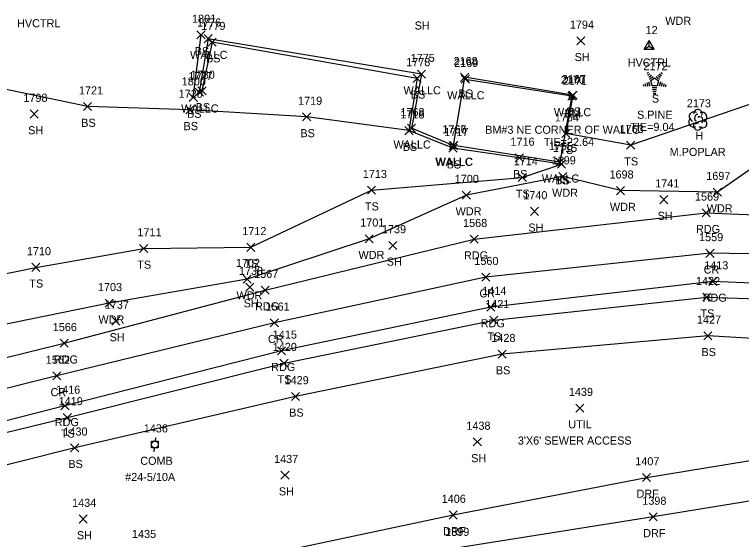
# Model space of a CAD drawing. Extents: x 1609623 to 1616187, y 756677 to 762826.
# Drawn here: x 1609877.2 to 1610056.5, y 761685.5 to 761815 of the extents above; entities that cross this region are included whole.
import ezdxf

# ---------------------------------------------------------------- set-up
doc = ezdxf.new("R2010")
doc.units = 0
for name, color, linetype in [('C_A', 7, 'Continuous'), ('C_C', 7, 'Continuous'), ('C_I', 7, 'Continuous'), ('CPBM', 7, 'Continuous'), ('CPSM', 7, 'Continuous'), ('L_A', 7, 'Continuous'), ('L_C', 7, 'Continuous'), ('L_I', 7, 'Continuous'), ('L_TIC', 7, 'Continuous'), ('LAWA', 7, 'Continuous'), ('LELB', 7, 'Continuous'), ('LTC', 7, 'Continuous'), ('LTD', 7, 'Continuous'), ('LW', 7, 'Continuous'), ('P_A', 7, 'Continuous'), ('P_I', 7, 'Continuous'), ('P_TIC', 7, 'Continuous'), ('PEU', 7, 'Continuous'), ('PRC', 7, 'Continuous'), ('R_A', 7, 'Continuous'), ('R_I', 7, 'Continuous'), ('R_TIC', 7, 'Continuous'), ('RDF', 7, 'Continuous'), ('U_A', 7, 'Continuous'), ('U_C', 7, 'Continuous'), ('U_I', 7, 'Continuous'), ('UDEFAULT', 7, 'Continuous'), ('UP', 7, 'Continuous')]:
    doc.layers.add(name, color=color, linetype=linetype)

msp = doc.modelspace()

# ---------------------------------------------------------------- linework, layer by layer
at = {"layer": 'CPBM'}
for p, q in [((1610014.04, 761794.09), (1610014.04, 761795.09)), ((1610014.04, 761795.09), (1610015.04, 761795.09)), ((1610015.04, 761794.09), (1610014.04, 761794.09)), ((1610014.54, 761794.59), (1610014.54, 761794.59)), ((1610014.54, 761794.59), (1610014.54, 761794.59)), ((1610015.04, 761795.09), (1610015.04, 761794.09))]:
    msp.add_line(p, q, dxfattribs=at)
at = {"layer": 'CPSM'}
for p, q in [((1610032.48, 761806.47), (1610033.73, 761808.63)), ((1610034.98, 761806.47), (1610033.73, 761808.63)), ((1610033.73, 761807.19), (1610033.73, 761808.63)), ((1610032.48, 761806.47), (1610033.73, 761807.19)), ((1610033.73, 761807.19), (1610033.73, 761807.19)), ((1610033.73, 761807.19), (1610034.98, 761806.47)), ((1610032.48, 761806.47), (1610034.98, 761806.47))]:
    msp.add_line(p, q, dxfattribs=at)
at = {"layer": 'L_TIC'}
for points in [[(1609922.17, 761808.99), (1609924.17, 761810.99)], [(1609924.17, 761808.99), (1609922.17, 761810.99)], [(1609923.94, 761808.06), (1609925.94, 761810.06)], [(1609925.94, 761808.06), (1609923.94, 761810.06)], [(1609924.95, 761807.21), (1609926.95, 761809.21)], [(1609926.95, 761807.21), (1609924.95, 761809.21)], [(1610015.85, 761807.53), (1610017.85, 761809.53)], [(1610017.85, 761807.53), (1610015.85, 761809.53)], [(1609976.58, 761799.32), (1609978.58, 761801.32)], [(1609978.58, 761799.32), (1609976.58, 761801.32)], [(1609975.48, 761798.27), (1609977.48, 761800.27)], [(1609977.48, 761798.27), (1609975.48, 761800.27)], [(1609987.2, 761798.53), (1609989.2, 761800.53)], [(1609989.2, 761798.53), (1609987.2, 761800.53)], [(1609987.36, 761798.09), (1609989.36, 761800.09)], [(1609989.36, 761798.09), (1609987.36, 761800.09)], [(1609921.75, 761794.84), (1609923.75, 761796.84)], [(1609923.75, 761794.84), (1609921.75, 761796.84)], [(1609922.41, 761795.17), (1609924.41, 761797.17)], [(1609924.41, 761795.17), (1609922.41, 761797.17)], [(1610013.68, 761793.92), (1610015.68, 761795.92)], [(1610015.68, 761793.92), (1610013.68, 761795.92)], [(1610013.92, 761794.1), (1610015.92, 761796.1)], [(1610015.92, 761794.1), (1610013.92, 761796.1)], [(1609920.27, 761793.53), (1609922.27, 761795.53)], [(1609922.27, 761793.53), (1609920.27, 761795.53)], [(1609894.19, 761791.3), (1609896.19, 761793.3)], [(1609896.19, 761791.3), (1609894.19, 761793.3)], [(1609919.43, 761790.48), (1609921.43, 761792.48)], [(1609921.43, 761790.48), (1609919.43, 761792.48)], [(1609881.04, 761789.47), (1609883.04, 761791.47)], [(1609883.04, 761789.47), (1609881.04, 761791.47)], [(1609948.24, 761788.75), (1609950.24, 761790.75)], [(1609950.24, 761788.75), (1609948.24, 761790.75)], [(1609973.47, 761785.37), (1609975.47, 761787.37)], [(1609975.47, 761785.37), (1609973.47, 761787.37)], [(1609974.1, 761785.94), (1609976.1, 761787.94)], [(1609976.1, 761785.94), (1609974.1, 761787.94)], [(1610012.18, 761784.65), (1610014.18, 761786.65)], [(1610014.18, 761784.65), (1610012.18, 761786.65)], [(1609984.41, 761781.67), (1609986.41, 761783.67)], [(1609986.41, 761781.67), (1609984.41, 761783.67)], [(1609984.54, 761781.69), (1609986.54, 761783.69)], [(1609986.54, 761781.69), (1609984.54, 761783.69)], [(1610028.16, 761781.79), (1610030.16, 761783.79)], [(1610030.16, 761781.79), (1610028.16, 761783.79)], [(1609984.32, 761781.03), (1609986.32, 761783.03)], [(1609986.32, 761781.03), (1609984.32, 761783.03)], [(1610000.68, 761778.63), (1610002.68, 761780.63)], [(1610002.68, 761778.63), (1610000.68, 761780.63)], [(1610010.71, 761777.56), (1610012.71, 761779.56)], [(1610012.71, 761777.56), (1610010.71, 761779.56)], [(1610011.12, 761777.1), (1610013.12, 761779.1)], [(1610013.12, 761777.1), (1610011.12, 761779.1)], [(1610011.12, 761777.1), (1610013.12, 761779.1)], [(1610013.12, 761777.1), (1610011.12, 761779.1)], [(1610011.41, 761774.03), (1610013.41, 761776.03)], [(1610013.41, 761774.03), (1610011.41, 761776.03)], [(1610001.42, 761773.81), (1610003.42, 761775.81)], [(1610003.42, 761773.81), (1610001.42, 761775.81)], [(1609964.21, 761770.67), (1609966.21, 761772.67)], [(1609966.21, 761770.67), (1609964.21, 761772.67)], [(1610025.67, 761770.55), (1610027.67, 761772.55)], [(1610027.67, 761770.55), (1610025.67, 761772.55)], [(1609987.62, 761769.46), (1609989.62, 761771.46)], [(1609989.62, 761769.46), (1609987.62, 761771.46)], [(1610049.54, 761770.19), (1610051.54, 761772.19)], [(1610051.54, 761770.19), (1610049.54, 761772.19)], [(1610036.32, 761768.34), (1610038.32, 761770.34)], [(1610038.32, 761768.34), (1610036.32, 761770.34)], [(1610004.44, 761765.44), (1610006.44, 761767.44)], [(1610006.44, 761765.44), (1610004.44, 761767.44)], [(1609963.66, 761758.68), (1609965.66, 761760.68)], [(1609965.66, 761758.68), (1609963.66, 761760.68)], [(1609908.04, 761756.29), (1609910.04, 761758.29)], [(1609910.04, 761756.29), (1609908.04, 761758.29)], [(1609934.48, 761756.57), (1609936.48, 761758.57)], [(1609936.48, 761756.57), (1609934.48, 761758.57)], [(1609969.5, 761757.04), (1609971.5, 761759.04)], [(1609971.5, 761757.04), (1609969.5, 761759.04)], [(1609881.42, 761751.62), (1609883.42, 761753.62)], [(1609883.42, 761751.62), (1609881.42, 761753.62)], [(1609933.55, 761748.72), (1609935.55, 761750.72)], [(1609935.55, 761748.72), (1609933.55, 761750.72)], [(1609934.22, 761746.74), (1609936.22, 761748.74)], [(1609936.22, 761746.74), (1609934.22, 761748.74)], [(1610046.96, 761744.26), (1610048.96, 761746.26)], [(1610048.96, 761744.26), (1610046.96, 761746.26)], [(1609899.52, 761742.76), (1609901.52, 761744.76)], [(1609901.52, 761742.76), (1609899.52, 761744.76)], [(1609901.14, 761738.39), (1609903.14, 761740.39)], [(1609903.14, 761738.39), (1609901.14, 761740.39)], [(1609994.4, 761738.57), (1609996.4, 761740.57)], [(1609996.4, 761738.57), (1609994.4, 761740.57)], [(1610047.19, 761734.72), (1610049.19, 761736.72)], [(1610049.19, 761734.72), (1610047.19, 761736.72)], [(1609996.47, 761730.21), (1609998.47, 761732.21)], [(1609998.47, 761730.21), (1609996.47, 761732.21)], [(1609942.65, 761728), (1609944.65, 761730)], [(1609944.65, 761728), (1609942.65, 761730)], [(1609945.49, 761719.77), (1609947.49, 761721.77)], [(1609947.49, 761719.77), (1609945.49, 761721.77)], [(1609889.2, 761714.59), (1609891.2, 761716.59)], [(1609891.2, 761714.59), (1609889.2, 761716.59)], [(1609990.32, 761708.53), (1609992.32, 761710.53)], [(1609992.32, 761708.53), (1609990.32, 761710.53)], [(1609891.01, 761707.1), (1609893.01, 761709.1)], [(1609893.01, 761707.1), (1609891.01, 761709.1)], [(1609942.89, 761700.33), (1609944.89, 761702.33)], [(1609944.89, 761700.33), (1609942.89, 761702.33)], [(1609893.08, 761689.51), (1609895.08, 761691.51)], [(1609895.08, 761689.51), (1609893.08, 761691.51)]]:
    msp.add_lwpolyline(points, dxfattribs=at)
at = {"layer": 'LAWA'}
msp.add_lwpolyline([(1610105.26, 761813.02), (1610140.61, 761813.42), (1610167.68, 761812.65), (1610195.19, 761811.82), (1610200.47, 761794.62), (1610201.65, 761767.6), (1610187.83, 761765.14), (1610147.91, 761771.28), (1610109.49, 761778.29), (1610068.49, 761778.93), (1610059.44, 761777.35), (1610050.54, 761771.19), (1610026.67, 761771.55), (1610012.41, 761775.03), (1609988.62, 761770.46), (1609964.66, 761759.68), (1609934.55, 761749.72), (1609900.52, 761743.76), (1609861.36, 761735.79), (1609834.63, 761731.47), (1609803.94, 761726.14)], dxfattribs=at)
at = {"layer": 'LELB'}
for points in [[(1609921.27, 761794.53), (1609923.17, 761809.99)], [(1609976.48, 761799.27), (1609925.95, 761808.21), (1609923.41, 761796.17)], [(1610012.12, 761778.1), (1610001.68, 761779.63), (1609985.32, 761782.03), (1609974.47, 761786.37), (1609949.24, 761789.75), (1609920.43, 761791.48), (1609895.19, 761792.3), (1609862.07, 761799.25), (1609844.22, 761803.39), (1609837.25, 761792.78), (1609798.06, 761802.79)], [(1609988.2, 761799.53), (1609985.41, 761782.67)], [(1610014.92, 761795.1), (1609988.2, 761799.53)], [(1609976.48, 761799.27), (1609974.47, 761786.37)], [(1610014.92, 761795.1), (1610013.18, 761785.65)], [(1610068.13, 761791.39), (1610060.09, 761793.42), (1610029.16, 761782.79), (1610013.18, 761785.65)], [(1609797.77, 761751.53), (1609825.21, 761750.42), (1609849.09, 761745.85), (1609882.42, 761752.62), (1609909.04, 761757.29), (1609935.48, 761757.57), (1609965.21, 761771.67), (1610002.42, 761774.81), (1610012.12, 761778.1)], [(1609807.34, 761695.39), (1609890.2, 761715.59), (1609943.65, 761729), (1609995.4, 761739.57), (1610047.96, 761745.26), (1610095.6, 761743.67), (1610138.67, 761738.82), (1610134.33, 761731.12)], [(1610134.33, 761731.12), (1610095.12, 761732.91), (1610048.19, 761735.72), (1609997.47, 761731.21), (1609946.49, 761720.77), (1609892.01, 761708.1), (1609809.24, 761687.22)]]:
    msp.add_lwpolyline(points, dxfattribs=at)
at = {"layer": 'LTC'}
for p, q in [((1610033.19, 761800.5), (1610033.54, 761800.76)), ((1610033.4, 761800.03), (1610033.93, 761800.42)), ((1610033.61, 761799.57), (1610034.31, 761800.08)), ((1610033.82, 761799.1), (1610034.69, 761799.74)), ((1610034.04, 761798.65), (1610035.05, 761799.38)), ((1610035.05, 761799.38), (1610036.05, 761798.66)), ((1610035.47, 761799.7), (1610036.28, 761799.11)), ((1610035.84, 761800.04), (1610036.52, 761799.55)), ((1610036.21, 761800.39), (1610036.76, 761799.99)), ((1610036.59, 761800.74), (1610037.01, 761800.44)), ((1610032.22, 761797.78), (1610032.37, 761797.31)), ((1610032.68, 761798), (1610032.89, 761797.34)), ((1610033.13, 761798.21), (1610033.4, 761797.38)), ((1610033.59, 761798.43), (1610033.92, 761797.41)), ((1610034.04, 761798.65), (1610034.43, 761797.45)), ((1610036.05, 761798.66), (1610035.66, 761797.45)), ((1610036.49, 761798.39), (1610036.15, 761797.35)), ((1610036.93, 761798.14), (1610036.64, 761797.25)), ((1610037.38, 761797.89), (1610037.14, 761797.16)), ((1610037.82, 761797.64), (1610037.63, 761797.06)), ((1610035.66, 761797.45), (1610034.43, 761797.45)), ((1610035.62, 761796.95), (1610034.48, 761796.95)), ((1610035.54, 761796.45), (1610034.55, 761796.45)), ((1610035.45, 761795.95), (1610034.62, 761795.95)), ((1610035.37, 761795.45), (1610034.69, 761795.45))]:
    msp.add_line(p, q, dxfattribs=at)
at = {"layer": 'LTD'}
msp.add_line((1610045.69, 761789.11), (1610045.69, 761789.11), dxfattribs=at)
msp.add_line((1610045.69, 761789.11), (1610045.69, 761789.11), dxfattribs=at)
msp.add_arc((1610045.74, 761790.55), 1.05, 335.5272, 180.9563, dxfattribs=at)
for centre, major_axis, ratio, start_param, end_param in [((1610044.9, 761789.78), (1.21, -0.51), 0.895232, 1.570796, 4.712389), ((1610045.48, 761789.57), (-0.208, -0.792), 0.645439, 3.141593, 6.283185), ((1610046.73, 761789.7), (-1.14, -0.48), 0.949671, 1.570796, 4.712389), ((1610044.61, 761788.41), (0.58, -1.04), 0.959034, 3.141593, 6.283185), ((1610046.19, 761788.95), (-0.5, 0.667), 0.989748, 3.141593, 6.283185), ((1610046.69, 761788.28), (-1.09, 0.79), 0.841452, 1.570796, 4.712389), ((1610045.69, 761787.61), (0.26, 1.06), 0.942809, 1.570796, 4.712389), ((1610045.23, 761788.36), (-0.625, -0.083), 0.423636, 0, 3.141593)]:
    msp.add_ellipse(centre, major_axis=major_axis, ratio=ratio, start_param=start_param, end_param=end_param, dxfattribs=at)
at = {"layer": 'LW'}
for points in [[(1609977.58, 761800.32), (1609924.94, 761809.06), (1609922.75, 761795.84)], [(1609977.58, 761800.32), (1609975.1, 761786.94)], [(1609988.36, 761799.09), (1610014.68, 761794.92)], [(1610014.68, 761794.92), (1610011.71, 761778.56)], [(1610011.71, 761778.56), (1609985.54, 761782.69), (1609985.41, 761782.67), (1609975.1, 761786.94)]]:
    msp.add_lwpolyline(points, dxfattribs=at)
at = {"layer": 'P_TIC'}
for points in [[(1610046.77, 761765.09), (1610048.77, 761767.09)], [(1610048.77, 761765.09), (1610046.77, 761767.09)], [(1609989.56, 761758.58), (1609991.56, 761760.58)], [(1609991.56, 761758.58), (1609989.56, 761760.58)], [(1610047.73, 761755.09), (1610049.73, 761757.09)], [(1610049.73, 761755.09), (1610047.73, 761757.09)], [(1609992.41, 761749.2), (1609994.41, 761751.2)], [(1609994.41, 761749.2), (1609992.41, 761751.2)], [(1610048.42, 761748.13), (1610050.42, 761750.13)], [(1610050.42, 761748.13), (1610048.42, 761750.13)], [(1609938.02, 761746.01), (1609940.02, 761748.01)], [(1609940.02, 761746.01), (1609938.02, 761748.01)], [(1609993.68, 761741.82), (1609995.68, 761743.82)], [(1609995.68, 761741.82), (1609993.68, 761743.82)], [(1609940.26, 761737.94), (1609942.26, 761739.94)], [(1609942.26, 761737.94), (1609940.26, 761739.94)], [(1609888.39, 761732.89), (1609890.39, 761734.89)], [(1609890.39, 761732.89), (1609888.39, 761734.89)], [(1609942, 761731.03), (1609944, 761733.03)], [(1609944, 761731.03), (1609942, 761733.03)], [(1609886.62, 761724.82), (1609888.62, 761726.82)], [(1609888.62, 761724.82), (1609886.62, 761726.82)], [(1609888.61, 761717.43), (1609890.61, 761719.43)], [(1609890.61, 761717.43), (1609888.61, 761719.43)]]:
    msp.add_lwpolyline(points, dxfattribs=at)
at = {"layer": 'PEU'}
for points in [[(1609803.09, 761712.98), (1609847.46, 761723.55), (1609889.39, 761733.89), (1609939.02, 761747.01), (1609990.56, 761759.58), (1610047.77, 761766.09), (1610098.04, 761763.99), (1610151.67, 761759.1), (1610189.68, 761755.64), (1610237.76, 761754.25), (1610264.31, 761756.11)], [(1610523.28, 761673.99), (1610480.04, 761689.74), (1610439, 761706.13), (1610392.08, 761720.87), (1610334.48, 761734.06), (1610288.63, 761739.63), (1610237.75, 761740.33), (1610189.36, 761741.54), (1610151.21, 761743.29), (1610095.63, 761747.13), (1610049.42, 761749.13), (1609994.68, 761742.82), (1609943, 761732.03), (1609889.61, 761718.43), (1609806.51, 761697.21)]]:
    msp.add_lwpolyline(points, dxfattribs=at)
at = {"layer": 'PRC'}
msp.add_lwpolyline([(1610601.8, 761670.75), (1610582.15, 761672.46), (1610527.05, 761683.5), (1610483.24, 761698.98), (1610440.53, 761715.33), (1610395.01, 761729.94), (1610335.18, 761743.5), (1610288.69, 761747.54), (1610237.99, 761746.29), (1610189.61, 761747.71), (1610150.7, 761750.53), (1610096.59, 761755.33), (1610048.73, 761756.09), (1609993.41, 761750.2), (1609941.26, 761738.94), (1609887.62, 761725.82), (1609805.01, 761705.08)], dxfattribs=at)
at = {"layer": 'R_TIC'}
for points in [[(1610032.07, 761699.76), (1610034.07, 761701.76)], [(1610034.07, 761699.76), (1610032.07, 761701.76)], [(1609984.37, 761690.5), (1609986.37, 761692.5)], [(1609986.37, 761690.5), (1609984.37, 761692.5)], [(1610033.71, 761690.02), (1610035.71, 761692.02)], [(1610035.71, 761690.02), (1610033.71, 761692.02)]]:
    msp.add_lwpolyline(points, dxfattribs=at)
at = {"layer": 'RDF'}
for points in [[(1609814.26, 761657.5), (1609880.33, 761669.23), (1609931.14, 761680.03), (1609985.37, 761691.5), (1610033.07, 761700.76), (1610082.25, 761708.78), (1610121.02, 761717.5), (1610147.57, 761728), (1610151.21, 761743.29)], [(1610189.36, 761741.54), (1610170.1, 761727.36), (1610123.54, 761709.71), (1610082.66, 761698.89), (1610034.71, 761691.02), (1609986.1, 761683.34), (1609933.94, 761672.88), (1609882.6, 761661.03), (1609815.24, 761649.06)]]:
    msp.add_lwpolyline(points, dxfattribs=at)
at = {"layer": 'UDEFAULT'}
for points in [[(1610015.61, 761716.88), (1610017.61, 761718.88)], [(1610017.61, 761716.88), (1610015.61, 761718.88)]]:
    msp.add_lwpolyline(points, dxfattribs=at)
at = {"layer": 'UP'}
for p, q in [((1609910.98, 761708.04), (1609910.98, 761709.71)), ((1609910.98, 761709.71), (1609912.64, 761709.71)), ((1609912.06, 761710.54), (1609911.81, 761709.71)), ((1609912.64, 761709.71), (1609912.64, 761708.04)), ((1609912.64, 761708.04), (1609910.98, 761708.04)), ((1609911.56, 761707.21), (1609911.81, 761708.04)), ((1609911.81, 761708.88), (1609911.81, 761708.88))]:
    msp.add_line(p, q, dxfattribs=at)
msp.add_circle((1609911.81, 761708.88), 0.833, dxfattribs=at)

# ---------------------------------------------------------------- texts
at = {"layer": 'C_A'}
for s, p in [('HVCTRL', (1609877.8, 761811.87)), ('HVCTRL', (1610028.42, 761802.19)), ('BM', (1610012.86, 761789.59))]:
    msp.add_text(s, height=2, dxfattribs=at).set_placement(p)
at = {"layer": 'C_C'}
for s, p in [('BM#3 NE CORNER OF WALLC', (1609993.26, 761785.59)), ('TIE=22.64', (1610007.72, 761782.59))]:
    msp.add_text(s, height=2, dxfattribs=at).set_placement(p)
at = {"layer": 'C_I'}
for s, p in [('12', (1610032.83, 761810.19)), ('2171', (1610012.41, 761797.59))]:
    msp.add_text(s, height=2, dxfattribs=at).set_placement(p)
at = {"layer": 'L_A'}
for s, p in [('WDR', (1610037.69, 761812.48)), ('SH', (1609975.87, 761811.31)), ('BS', (1609921.61, 761804.99)), ('WALLC', (1609920.48, 761804.06)), ('BS', (1609924.39, 761803.21)), ('SH', (1610015.33, 761803.53)), ('WALLC', (1609973.12, 761795.32)), ('BS', (1609974.92, 761794.27)), ('WALLC', (1609983.89, 761794.09)), ('BS', (1609986.64, 761794.53)), ('S', (1610034.38, 761793.29)), ('WALLC', (1609918.29, 761790.84)), ('BS', (1609921.85, 761791.17)), ('BS', (1610013.36, 761790.1)), ('BS', (1609919.72, 761789.53)), ('WALLC', (1610010.22, 761789.92)), ('BS', (1609893.63, 761787.3)), ('SH', (1609880.53, 761785.47)), ('BS', (1609918.87, 761786.48)), ('BS', (1609947.68, 761784.75)), ('H', (1610045.12, 761784.11)), ('WALLC', (1609970.64, 761781.94)), ('BS', (1609972.91, 761781.37)), ('TS', (1610011.59, 761780.65)), ('WALLC', (1609980.95, 761777.67)), ('WALLC', (1609981.07, 761777.69)), ('TS', (1610027.57, 761777.79)), ('BS', (1609983.76, 761777.03)), ('BS', (1610000.12, 761774.63)), ('WALLC', (1610007.24, 761773.56)), ('TS', (1610010.53, 761773.1)), ('BS', (1610010.56, 761773.1)), ('TS', (1610000.83, 761769.81)), ('WDR', (1610009.77, 761770.03)), ('TS', (1609963.62, 761766.67)), ('WDR', (1609985.98, 761765.46)), ('WDR', (1610024.04, 761766.55)), ('WDR', (1610047.91, 761766.19)), ('SH', (1610035.81, 761764.34)), ('SH', (1610003.92, 761761.44)), ('WDR', (1609962.02, 761754.68)), ('TS', (1609933.89, 761752.57)), ('SH', (1609968.99, 761753.04)), ('TS', (1609907.45, 761752.29)), ('TS', (1609880.83, 761747.62)), ('WDR', (1609931.91, 761744.72)), ('SH', (1609933.7, 761742.74)), ('TS', (1610046.37, 761740.26)), ('WDR', (1609897.88, 761738.76)), ('TS', (1609993.81, 761734.57)), ('SH', (1609900.63, 761734.39)), ('BS', (1610046.63, 761730.72)), ('BS', (1609995.91, 761726.21)), ('TS', (1609942.06, 761724)), ('BS', (1609944.93, 761715.77)), ('TS', (1609888.61, 761710.59)), ('SH', (1609989.81, 761704.53)), ('BS', (1609890.45, 761703.1)), ('SH', (1609942.38, 761696.33)), ('SH', (1609892.56, 761685.51))]:
    msp.add_text(s, height=2, dxfattribs=at).set_placement(p)
at = {"layer": 'L_C'}
for s, p in [('S.PINE', (1610030.72, 761789.29)), ('TIE=9.04', (1610029.04, 761786.29)), ('M.POPLAR', (1610038.77, 761780.11))]:
    msp.add_text(s, height=2, dxfattribs=at).set_placement(p)
at = {"layer": 'L_I'}
for s, p in [('1801', (1609920.97, 761812.99)), ('1776', (1609922.2, 761812.06)), ('1779', (1609923.25, 761811.21)), ('1794', (1610014.15, 761811.53)), ('1775', (1609974.89, 761803.32)), ('1778', (1609973.79, 761802.27)), ('2168', (1609985.46, 761802.53)), ('2169', (1609985.61, 761802.09)), ('2172', (1610032.3, 761801.29)), ('1780', (1609920.63, 761799.17)), ('1800', (1609918.42, 761797.53)), ('1777', (1609920.06, 761798.84)), ('2170', (1610011.9, 761797.92)), ('2167', (1610012.18, 761798.1)), ('1721', (1609893.06, 761795.3)), ('1720', (1609917.65, 761794.48)), ('1798', (1609879.35, 761793.47)), ('1719', (1609947.11, 761792.75)), ('2173', (1610043, 761792.11)), ('1718', (1609972.35, 761789.37)), ('1768', (1609972.36, 761789.94)), ('1764', (1610010.44, 761788.65)), ('1767', (1609982.67, 761785.67)), ('1766', (1609982.74, 761785.69)), ('1717', (1609983.19, 761785.03)), ('1763', (1610026.42, 761785.79)), ('1716', (1609999.5, 761782.63)), ('1765', (1610008.97, 761781.56)), ('1715', (1610009.99, 761781.1)), ('1715', (1610009.99, 761781.1)), ('1714', (1610000.3, 761777.81)), ('1699', (1610009.66, 761778.03)), ('1713', (1609963.08, 761774.67)), ('1698', (1610023.93, 761774.55)), ('1697', (1610047.8, 761774.19)), ('1700', (1609985.76, 761773.46)), ('1741', (1610035.2, 761772.34)), ('1740', (1610002.66, 761769.44)), ('1701', (1609962.45, 761762.68)), ('1711', (1609907.48, 761760.29)), ('1712', (1609933.35, 761760.57)), ('1739', (1609967.8, 761761.04)), ('1710', (1609880.21, 761755.62)), ('1702', (1609931.77, 761752.72)), ('1738', (1609932.52, 761750.74)), ('1422', (1610045.27, 761748.26)), ('1703', (1609897.75, 761746.76)), ('1737', (1609899.45, 761742.39)), ('1421', (1609993.28, 761742.57)), ('1427', (1610045.5, 761738.72)), ('1428', (1609994.78, 761734.21)), ('1420', (1609940.87, 761732)), ('1429', (1609943.79, 761723.77)), ('1419', (1609888.06, 761718.59)), ('1438', (1609988.63, 761712.53)), ('1430', (1609889.23, 761711.1)), ('1437', (1609941.2, 761704.33)), ('1434', (1609891.38, 761693.51))]:
    msp.add_text(s, height=2, dxfattribs=at).set_placement(p)
at = {"layer": 'LTC'}
msp.add_text('.', height=1.04, rotation=270, dxfattribs=at).set_placement((1610034.94, 761798.4))
at = {"layer": 'P_A'}
for s, p in [('RDG', (1610045.26, 761761.09)), ('RDG', (1609988.04, 761754.58)), ('CR', (1610047.16, 761751.09)), ('CR', (1609991.85, 761745.2)), ('RDG', (1610046.91, 761744.13)), ('RDG', (1609936.51, 761742.01)), ('RDG', (1609992.17, 761737.82)), ('CR', (1609939.69, 761733.94)), ('RDG', (1609886.88, 761728.89)), ('RDG', (1609940.49, 761727.03)), ('CR', (1609886.05, 761720.82)), ('RDG', (1609887.1, 761713.43))]:
    msp.add_text(s, height=2, dxfattribs=at).set_placement(p)
at = {"layer": 'P_I'}
for s, p in [('1569', (1610045.02, 761769.09)), ('1568', (1609987.82, 761762.58)), ('1559', (1610046.03, 761759.09)), ('1560', (1609990.59, 761753.2)), ('1413', (1610047.29, 761752.13)), ('1567', (1609936.28, 761750.01)), ('1414', (1609992.56, 761745.82)), ('1561', (1609939.09, 761741.94)), ('1566', (1609886.6, 761736.89)), ('1415', (1609940.87, 761735.03)), ('1562', (1609884.88, 761728.82)), ('1416', (1609887.43, 761721.43))]:
    msp.add_text(s, height=2, dxfattribs=at).set_placement(p)
at = {"layer": 'R_A'}
for p in [(1610030.6, 761695.76), (1609982.9, 761686.5), (1610032.25, 761686.02)]:
    msp.add_text('DRF', height=2, dxfattribs=at).set_placement(p)
at = {"layer": 'R_I'}
for s, p in [('1407', (1610030.29, 761703.76)), ('1406', (1609982.54, 761694.5)), ('1398', (1610032.02, 761694.02)), ('1399', (1609983.4, 761686.34))]:
    msp.add_text(s, height=2, dxfattribs=at).set_placement(p)
at = {"layer": 'U_A'}
for s, p in [('UTIL', (1610013.77, 761712.88)), ('COMB', (1609908.19, 761703.88))]:
    msp.add_text(s, height=2, dxfattribs=at).set_placement(p)
at = {"layer": 'U_C'}
for s, p in [("3'X6' SEWER ACCESS", (1610001.32, 761708.88)), ('#24-5/10A', (1609904.46, 761699.88))]:
    msp.add_text(s, height=2, dxfattribs=at).set_placement(p)
at = {"layer": 'U_I'}
for s, p in [('1439', (1610013.91, 761720.88)), ('1436', (1609909.06, 761711.88)), ('1435', (1609906.15, 761685.82))]:
    msp.add_text(s, height=2, dxfattribs=at).set_placement(p)

doc.saveas('drawing.dxf')
